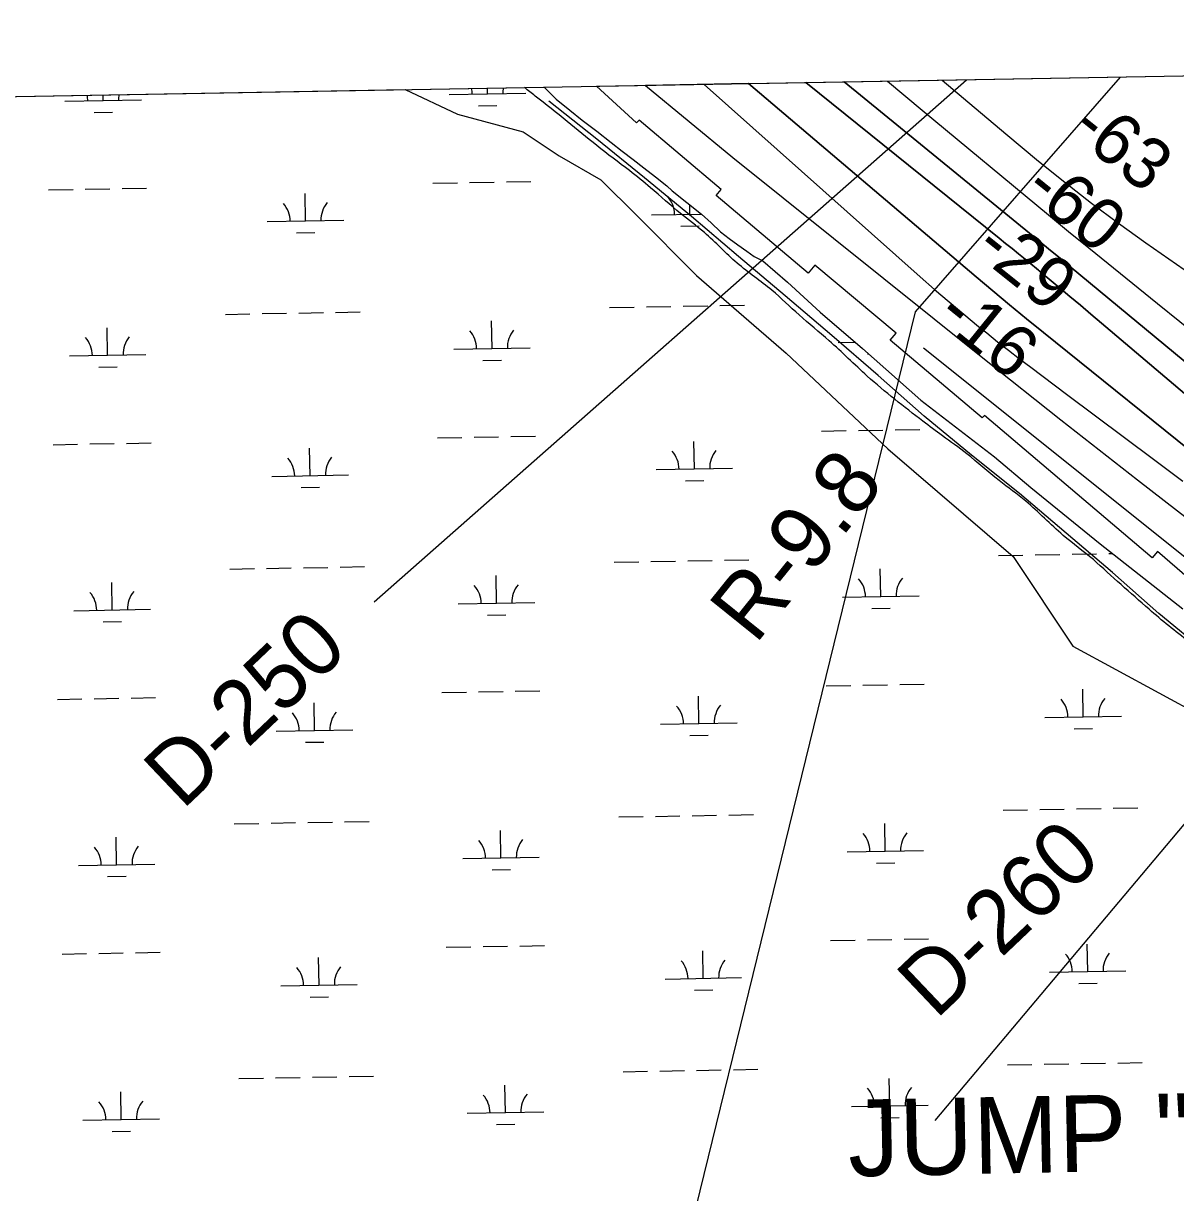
# Model space of a CAD drawing. Extents: x 3903937 to 3942190, y 260677 to 286651.
# Drawn here: x 3914342 to 3915846, y 282878 to 284405 of the extents above; entities that cross this region are included whole.
import ezdxf

# ---------------------------------------------------------------- set-up
doc = ezdxf.new("R2010")
doc.units = 0
for name, color, linetype in [('V-CHAN-NAID', 7, 'Continuous'), ('V-GRID-FRAM', 7, 'Continuous'), ('V-RIVR-EDGE', 7, 'Continuous'), ('V-RIVR-RANG', 7, 'Continuous'), ('V-RIVR-RANG-IDEN', 7, 'Continuous'), ('V-RRAP-FSHR', 7, 'Continuous'), ('V-RRAP-RVMT', 7, 'Continuous'), ('V-SITE-VEGE', 7, 'Continuous'), ('V-TOPO-DPTH', 7, 'Continuous'), ('V-TOPO-MAJR', 7, 'Continuous'), ('V-TOPO-MINR', 7, 'Continuous'), ('V-UTIL-LINE', 7, 'Continuous'), ('V-WETL-SWMP', 7, 'Continuous')]:
    doc.layers.add(name, color=color, linetype=linetype)

msp = doc.modelspace()

# ---------------------------------------------------------------- linework, layer by layer
at = {"layer": 'V-GRID-FRAM'}
msp.add_lwpolyline([(3907892.2, 284196.1), (3939773.2, 284757.2), (3940101.1, 266577.6), (3908204.3, 266016.2), (3907892.2, 284196.1)], dxfattribs=at)
at = {"layer": 'V-RIVR-EDGE'}
for points in [[(3915738.9, 283704.7), (3915699.6, 283736.4), (3915674.9, 283758.8), (3915650.7, 283781.1), (3915615.8, 283807.9), (3915573.6, 283843), (3915541.7, 283866.4), (3915516.4, 283885.4), (3915443.7, 283944.3), (3915393.8, 283990.6), (3915354.6, 284024.2), (3915319.2, 284056.4), (3915273.7, 284091.9), (3915231, 284131.8), (3915200, 284156.7), (3915160.7, 284190.3), (3915133.1, 284212.7), (3915090.5, 284245.3), (3915051.7, 284277), (3915010, 284310.1), (3914995.9, 284321.1)], [(3917425.1, 282263.8), (3917389, 282294.2), (3917376.9, 282301.5), (3917364.7, 282305.9), (3917358.9, 282312.7), (3917351.7, 282313.2), (3917339.5, 282313.8), (3917337.6, 282316.7), (3917335.7, 282327.9), (3917333.2, 282330.8), (3917324.5, 282334.2), (3917318.2, 282334.7), (3917313.8, 282338.1), (3917308, 282350.3), (3917295.5, 282366.8), (3917283.8, 282379), (3917272.2, 282386.3), (3917256.7, 282392.6), (3917245, 282398), (3917231.4, 282406.8), (3917219.3, 282412.6), (3917183.4, 282425.8), (3917138.3, 282440), (3917074.7, 282459.6), (3917032, 282479.1), (3916988.4, 282500.1), (3916967.5, 282515.7), (3916953.5, 282531.3), (3916939.4, 282546.9), (3916923.4, 282556.6), (3916909.4, 282558.6), (3916896.3, 282564), (3916886.6, 282574.7), (3916876.4, 282580.1), (3916858.4, 282585), (3916838.5, 282588.4), (3916812.3, 282597.2), (3916792, 282609.9), (3916782.3, 282615.7), (3916776, 282619.6), (3916763.8, 282627.4), (3916749.3, 282634.3), (3916741, 282637.7), (3916730.4, 282642.1), (3916723.6, 282648.4), (3916721.7, 282654.3), (3916721.7, 282661.1), (3916724.1, 282668.3), (3916732.9, 282687.7), (3916733.4, 282696), (3916730.5, 282710.6), (3916725.2, 282723.7), (3916724.8, 282730.5), (3916727.2, 282735.3), (3916735.5, 282744.1), (3916736.9, 282748.4), (3916736.5, 282752.3), (3916730.2, 282755.7), (3916729.2, 282758.2), (3916731.6, 282760.1), (3916731.6, 282763.5), (3916727.8, 282770.8), (3916727.3, 282772.7), (3916727.8, 282778.1), (3916727.8, 282783.9), (3916726.9, 282799), (3916725.5, 282818.4), (3916729.9, 282838.8), (3916731.4, 282846.1), (3916733.8, 282854.8), (3916737.7, 282862.1), (3916742.1, 282864.5), (3916751.8, 282863.5), (3916755.7, 282865.4), (3916757.2, 282868.8), (3916756.2, 282873.2), (3916756.2, 282883.9), (3916757.7, 282894.1), (3916764, 282902.3), (3916767, 282910.1), (3916770.4, 282913), (3916781, 282908.1), (3916789.3, 282907.6), (3916789.3, 282910), (3916782, 282918.8), (3916778.7, 282923.6), (3916763.6, 282935.3), (3916726.8, 282963.6), (3916714.2, 282972.9), (3916689, 282991.4), (3916632.3, 283034.2), (3916610, 283048.9), (3916578, 283066.9), (3916543, 283088.9), (3916510.1, 283112.7), (3916469.8, 283140.5), (3916444.2, 283160.5), (3916369, 283219), (3916281.3, 283284.2), (3916175.1, 283366.6), (3916089.8, 283429.9), (3915988, 283506.4), (3915917.7, 283560), (3915863.9, 283597.5), (3915811.6, 283639.9), (3915738.9, 283704.7)]]:
    msp.add_spline(points, degree=3, dxfattribs=at)
at = {"layer": 'V-RIVR-RANG'}
for p, q in [((3914800, 283649.7), (3915573.3, 284331.3)), ((3915532.3, 282972.2), (3916510.4, 284135.6))]:
    msp.add_line(p, q, dxfattribs=at)
at = {"layer": 'V-RRAP-FSHR'}
msp.add_lwpolyline([(3915885.9, 283583.8), (3915824.2, 283634.5), (3915763.8, 283687.8), (3915703.3, 283739.4), (3915642.5, 283790.9), (3915579.9, 283841.3), (3915518, 283891.9), (3915458.1, 283945), (3915397.5, 283997.2), (3915336.5, 284049), (3915275.4, 284100.6), (3915214.1, 284152.6), (3915152.6, 284203.2), (3915090.5, 284253.6), (3915027.9, 284303.4)], dxfattribs=at)
at = {"layer": 'V-RRAP-RVMT'}
for p, q in [((3915090, 284322.8), (3915958.5, 284338.1)), ((3915142.3, 284275.1), (3915090, 284322.8)), ((3915145.7, 284278.7), (3915142.3, 284275.1)), ((3915253.1, 284188), (3915145.7, 284278.7)), ((3915246.3, 284180.1), (3915253.1, 284188)), ((3915366.5, 284078.7), (3915246.3, 284180.1)), ((3915375.4, 284089.4), (3915366.5, 284078.7)), ((3915481.3, 284000.2), (3915375.4, 284089.4)), ((3915473.6, 283991.2), (3915481.3, 284000.2)), ((3915593.8, 283889.8), (3915473.6, 283991.2)), ((3915596.6, 283893.1), (3915593.8, 283889.8)), ((3915815.8, 283707), (3915596.6, 283893.1)), ((3915822.8, 283715.3), (3915815.8, 283707)), ((3915926.5, 283624.8), (3915822.8, 283715.3))]:
    msp.add_line(p, q, dxfattribs=at)
at = {"layer": 'V-SITE-VEGE'}
for p, q in [((3913226.6, 284290), (3914840.4, 284318.4)), ((3914840.4, 284318.4), (3914908.5, 284286.6)), ((3914908.5, 284286.6), (3914994.4, 284263.2)), ((3914994.4, 284263.2), (3915041.2, 284231.9)), ((3915041.2, 284231.9), (3915095.8, 284200.7)), ((3915095.8, 284200.7), (3915142.6, 284153.9)), ((3915142.6, 284153.9), (3915220.7, 284075.8)), ((3915220.7, 284075.8), (3915337.7, 283974.3)), ((3915337.7, 283974.3), (3915470.4, 283849.4)), ((3915470.4, 283849.4), (3915634.2, 283708.9)), ((3915634.2, 283708.9), (3915712.2, 283591.8)), ((3915712.2, 283591.8), (3915883.9, 283498.1))]:
    msp.add_line(p, q, dxfattribs=at)
at = {"layer": 'V-TOPO-DPTH'}
msp.add_line((3915288.4, 284326.3), (3915154, 284323.9), dxfattribs=at)
for points in [[(3915154, 284323.9), (3915210.9, 284276.7), (3915268.2, 284230), (3915596.7, 283966.6), (3915696.3, 283887.4), (3915796.4, 283808.7), (3915897.2, 283731)], [(3915895.2, 283822.9), (3915673.8, 284001.2), (3915651.6, 284019.2), (3915629.5, 284037.4), (3915607.5, 284055.7), (3915585.7, 284074.1), (3915288.4, 284326.3)], [(3915288.4, 284326.3), (3915585.7, 284074.1), (3915607.5, 284055.7), (3915629.5, 284037.4), (3915651.6, 284019.2), (3915673.8, 284001.2), (3915895.2, 283822.9)], [(3916245.8, 283593.1), (3915749.5, 284013.5), (3915735.7, 284025.2), (3915721.9, 284036.9), (3915708, 284048.5), (3915694.2, 284060.2), (3915668.2, 284082), (3915667.4, 284082.7), (3915664.8, 284084.8), (3915649.7, 284097.1), (3915641.2, 284104), (3915632.8, 284110.8), (3915624.3, 284117.7), (3915615.9, 284124.5), (3915363.6, 284327.6)], [(3916245.8, 283593.1), (3915749.5, 284013.5), (3915735.7, 284025.2), (3915721.9, 284036.9), (3915708, 284048.5), (3915694.2, 284060.2), (3915668.2, 284082), (3915667.4, 284082.7), (3915664.8, 284084.8), (3915649.7, 284097.1), (3915641.2, 284104), (3915632.8, 284110.8), (3915624.3, 284117.7), (3915615.9, 284124.5), (3915363.6, 284327.6)], [(3915413.4, 284328.5), (3915660.4, 284127), (3915672.8, 284116.8), (3915685.2, 284106.6), (3915697.6, 284096.4), (3915710, 284086.2), (3916138.8, 283731.5)], [(3916138.8, 283731.5), (3915710, 284086.2), (3915697.6, 284096.4), (3915685.2, 284106.6), (3915672.8, 284116.8), (3915660.4, 284127), (3915413.4, 284328.5)]]:
    msp.add_lwpolyline(points, dxfattribs=at)
at = {"layer": 'V-TOPO-MAJR'}
msp.add_lwpolyline([(3915469.9, 284329.5), (3915515.3, 284291.7), (3915680.3, 284154.8), (3915693.4, 284144), (3915706.6, 284133.2), (3915719.7, 284122.4), (3915732.9, 284111.7), (3915822.6, 284039), (3915880.8, 283992)], dxfattribs=at)
at = {"layer": 'V-TOPO-MINR'}
for points in [[(3915154, 284323.9), (3915210.9, 284276.7), (3915268.2, 284230), (3915596.7, 283966.6), (3915696.3, 283887.4), (3915796.4, 283808.7), (3915897.2, 283731), (3915998.4, 283653.8), (3916141.4, 283545.9), (3916171.5, 283523.1), (3916201.5, 283500.4), (3916231.6, 283477.6), (3916261.6, 283454.7), (3916269, 283449.1), (3916302.5, 283423.3), (3916335.9, 283397.3), (3916369, 283370.9), (3916401.9, 283344.3), (3916773.8, 283040.4), (3916800.9, 283018), (3916827.8, 282995.5), (3916854.4, 282972.6), (3916880.9, 282949.6), (3916960.8, 282879.2)], [(3915230.6, 284325.3), (3915512.8, 284074.1), (3915531.6, 284057.6), (3915550.6, 284041.2), (3915569.7, 284025.1), (3915589.1, 284009.3), (3915599.6, 284000.7), (3915613.9, 283989.3), (3915628.2, 283978), (3915642.6, 283966.9), (3915657.2, 283955.9), (3915703.8, 283920.9), (3915741.7, 283892.5), (3915779.6, 283864.1), (3915817.6, 283835.7), (3915855.5, 283807.3)], [(3915288.4, 284326.3), (3915585.7, 284074.1), (3915607.5, 284055.7), (3915629.5, 284037.4), (3915651.6, 284019.2), (3915673.8, 284001.2), (3915895.2, 283822.9)], [(3915363.6, 284327.6), (3915615.9, 284124.5), (3915624.3, 284117.7), (3915632.8, 284110.8), (3915641.2, 284104), (3915649.7, 284097.1), (3915664.8, 284084.8), (3915667.4, 284082.7), (3915668.2, 284082), (3915694.2, 284060.2), (3915708, 284048.5), (3915721.9, 284036.9), (3915735.7, 284025.2), (3915749.5, 284013.5), (3916245.8, 283593.1)], [(3915413.4, 284328.5), (3915660.4, 284127), (3915672.8, 284116.8), (3915685.2, 284106.6), (3915697.6, 284096.4), (3915710, 284086.2), (3916138.8, 283731.5)], [(3915541.5, 284330.7), (3915569.3, 284307.1), (3915624.5, 284260.8), (3915667.3, 284225.2), (3915701.6, 284197.4), (3915736.3, 284170.2), (3915771.7, 284143.9), (3915807.6, 284118.3), (3915997.5, 283985.9)], [(3915517.1, 283981.1), (3915943, 283640.3), (3915980.6, 283610.4), (3916018.4, 283580.7), (3916056.4, 283551.3), (3916094.6, 283522.1), (3916113.7, 283507.5), (3916142.5, 283485.8), (3916171.3, 283464.1), (3916200.1, 283442.5), (3916229.1, 283421), (3916398.9, 283295.1), (3916468.5, 283242.9), (3916537.7, 283190.1), (3916606.2, 283136.5), (3916674.4, 283082.3), (3916778, 282998.8), (3916793.9, 282985.9), (3916809.7, 282972.8), (3916825.3, 282959.5), (3916840.7, 282946), (3916896.5, 282897)]]:
    msp.add_lwpolyline(points, dxfattribs=at)
at = {"layer": 'V-UTIL-LINE'}
msp.add_lwpolyline([(3915773.8, 284334.8), (3915506, 284028.1), (3914530.5, 280044.6)], dxfattribs=at)
at = {"layer": 'V-WETL-SWMP'}
for p, q in [((3913193.2, 284289.4), (3915021.6, 284321.6)), ((3914446, 284304.2), (3914445.9, 284311.4)), ((3914897.8, 284312.1), (3914997.8, 284313.9)), ((3914947.8, 284313), (3914947.7, 284320.3)), ((3915021.6, 284321.6), (3915037.6, 284305.8)), ((3914396, 284303.3), (3914496, 284305.1)), ((3914936.1, 284297.4), (3914960.1, 284297.8)), ((3915037.6, 284305.8), (3915055.2, 284291.6)), ((3914434.3, 284288.5), (3914458.3, 284289)), ((3915055.2, 284291.6), (3915071.4, 284278.6)), ((3915071.4, 284278.6), (3915090.4, 284264.2)), ((3915090.4, 284264.2), (3915109.4, 284249.4)), ((3915109.4, 284249.4), (3915123.8, 284238.2)), ((3915123.8, 284238.2), (3915138, 284227.2)), ((3915138, 284227.2), (3915151.8, 284216.2)), ((3915151.8, 284216.2), (3915167, 284204.6)), ((3915167, 284204.6), (3915181.8, 284193)), ((3914374.6, 284187.5), (3914406.6, 284188)), ((3914422.6, 284188.3), (3914454.6, 284188.9)), ((3914470.6, 284189.2), (3914502.6, 284189.7)), ((3914876.4, 284196.3), (3914908.4, 284196.9)), ((3914924.4, 284197.1), (3914956.4, 284197.7)), ((3914972.4, 284198), (3915004.4, 284198.6)), ((3915181.8, 284193), (3915189, 284186.4)), ((3915189, 284186.4), (3915227, 284155.8)), ((3914710.2, 284146.9), (3914709.6, 284182.9)), ((3915162.1, 284154.9), (3915226.8, 284156)), ((3915212.1, 284155.8), (3915211.8, 284168.1)), ((3915227, 284155.8), (3915239.8, 284144.7)), ((3914660.2, 284146.1), (3914760.2, 284147.8)), ((3915200.3, 284140.1), (3915224.3, 284140.6)), ((3915239.8, 284144.7), (3915252.2, 284132.9)), ((3914698.5, 284131.3), (3914722.5, 284131.7)), ((3915252.2, 284132.9), (3915263.4, 284124.1)), ((3915263.4, 284124.1), (3915274.6, 284115.9)), ((3915274.6, 284115.9), (3915286.2, 284107.3)), ((3915286.2, 284107.3), (3915295.8, 284100.5)), ((3915295.8, 284100.5), (3915307.2, 284094.8)), ((3915307.2, 284094.8), (3915339.6, 284067.2)), ((3915339.6, 284067.2), (3915382.3, 284028)), ((3915107.3, 284033.8), (3915139.3, 284034.4)), ((3915155.3, 284034.7), (3915187.3, 284035.2)), ((3915203.3, 284035.5), (3915235.3, 284036.1)), ((3915251.3, 284036.4), (3915283.3, 284036.9)), ((3914605.5, 284025), (3914637.5, 284025.6)), ((3914653.5, 284025.9), (3914685.5, 284026.4)), ((3914701.5, 284026.7), (3914733.5, 284027.3)), ((3914749.5, 284027.5), (3914781.5, 284028.1)), ((3915382.3, 284028), (3915437.4, 283980.3)), ((3914451.8, 283971.6), (3914451.2, 284007.5)), ((3914953.7, 283980.4), (3914953, 284016.4)), ((3915405.5, 283988.3), (3915427.7, 283988.7)), ((3914401.8, 283970.7), (3914501.8, 283972.4)), ((3914903.7, 283979.5), (3915003.7, 283981.3)), ((3915437.4, 283980.3), (3915513.4, 283913.1)), ((3915443.8, 283973.6), (3915445, 283973.6)), ((3914440.1, 283955.9), (3914464.1, 283956.3)), ((3914941.9, 283964.7), (3914965.9, 283965.2)), ((3915513.4, 283913.1), (3915609.6, 283838.9)), ((3914882.3, 283863.7), (3914914.3, 283864.2)), ((3914930.3, 283864.5), (3914962.3, 283865.1)), ((3914978.3, 283865.4), (3915010.3, 283865.9)), ((3915384.1, 283872.5), (3915416.1, 283873.1)), ((3915432.1, 283873.4), (3915464.1, 283873.9)), ((3915480.1, 283874.2), (3915512.1, 283874.8)), ((3914380.5, 283854.8), (3914412.5, 283855.4)), ((3914428.5, 283855.7), (3914460.5, 283856.3)), ((3914476.5, 283856.5), (3914508.5, 283857.1)), ((3914716.1, 283814.3), (3914715.4, 283850.3)), ((3915217.9, 283823.1), (3915217.3, 283859.1)), ((3915609.6, 283838.9), (3915657.2, 283798.9)), ((3915167.9, 283822.3), (3915267.9, 283824)), ((3914666.1, 283813.4), (3914766.1, 283815.2)), ((3915206.2, 283807.5), (3915230.2, 283807.9)), ((3914704.4, 283798.7), (3914728.4, 283799.1)), ((3915657.2, 283798.9), (3915747.6, 283725.1)), ((3915711, 283711.7), (3915743, 283712.3)), ((3915747.6, 283725.1), (3915855.9, 283640.6)), ((3915759, 283712.6), (3915763.6, 283712.7)), ((3915113.2, 283701.2), (3915145.2, 283701.8)), ((3915161.2, 283702.1), (3915193.2, 283702.6)), ((3915209.2, 283702.9), (3915241.2, 283703.5)), ((3915257.2, 283703.8), (3915289.2, 283704.3)), ((3915615, 283710), (3915647, 283710.6)), ((3915663, 283710.9), (3915695, 283711.5)), ((3914611.4, 283692.4), (3914643.4, 283692.9)), ((3914659.4, 283693.2), (3914691.4, 283693.8)), ((3914707.4, 283694.1), (3914739.3, 283694.6)), ((3914755.3, 283694.9), (3914787.3, 283695.5)), ((3914959.5, 283647.8), (3914958.9, 283683.8)), ((3915461.4, 283656.6), (3915460.7, 283692.6)), ((3914457.7, 283638.9), (3914457.1, 283674.9)), ((3915411.4, 283655.7), (3915511.3, 283657.5)), ((3914407.7, 283638), (3914507.7, 283639.8)), ((3914909.5, 283646.9), (3915009.5, 283648.6)), ((3915449.6, 283641), (3915473.6, 283641.4)), ((3914446, 283623.3), (3914470, 283623.7)), ((3914947.8, 283632.1), (3914971.8, 283632.5)), ((3914888.2, 283531.1), (3914920.2, 283531.6)), ((3914936.1, 283531.9), (3914968.1, 283532.5)), ((3914984.1, 283532.7), (3915016.1, 283533.3)), ((3915390, 283539.9), (3915422, 283540.5)), ((3915438, 283540.7), (3915470, 283541.3)), ((3915486, 283541.6), (3915518, 283542.1)), ((3915725.6, 283499.4), (3915725, 283535.4)), ((3914386.3, 283522.2), (3914418.3, 283522.8)), ((3914434.3, 283523.1), (3914466.3, 283523.6)), ((3914482.3, 283523.9), (3914514.3, 283524.5)), ((3914721.9, 283481.7), (3914721.3, 283517.7)), ((3915223.8, 283490.5), (3915223.1, 283526.5)), ((3915675.6, 283498.5), (3915775.6, 283500.2)), ((3914671.9, 283480.8), (3914771.9, 283482.6)), ((3915173.8, 283489.6), (3915273.8, 283491.4)), ((3915713.9, 283483.7), (3915737.9, 283484.1)), ((3915212, 283474.9), (3915236, 283475.3)), ((3914710.2, 283466.1), (3914734.2, 283466.5)), ((3915620.9, 283377.4), (3915652.9, 283378)), ((3915668.9, 283378.3), (3915700.9, 283378.8)), ((3915716.9, 283379.1), (3915748.9, 283379.7)), ((3915764.9, 283380), (3915796.9, 283380.5)), ((3914665.2, 283360.6), (3914697.2, 283361.2)), ((3914713.2, 283361.4), (3914745.2, 283362)), ((3914761.2, 283362.3), (3914793.2, 283362.9)), ((3915119.1, 283368.6), (3915151, 283369.2)), ((3915167, 283369.4), (3915199, 283370)), ((3915215, 283370.3), (3915247, 283370.8)), ((3915263, 283371.1), (3915295, 283371.7)), ((3914617.2, 283359.8), (3914649.2, 283360.3)), ((3914965.4, 283315.1), (3914964.7, 283351.1)), ((3915467.2, 283324), (3915466.6, 283360)), ((3914463.5, 283306.3), (3914462.9, 283342.3)), ((3914915.4, 283314.3), (3915015.4, 283316)), ((3915417.2, 283323.1), (3915517.2, 283324.9)), ((3914413.6, 283305.4), (3914513.5, 283307.2)), ((3914953.7, 283299.5), (3914977.6, 283299.9)), ((3915455.5, 283308.3), (3915479.5, 283308.8)), ((3914451.8, 283290.7), (3914475.8, 283291.1)), ((3915395.8, 283207.3), (3915427.8, 283207.8)), ((3915443.8, 283208.1), (3915475.8, 283208.7)), ((3915491.8, 283209), (3915523.8, 283209.5)), ((3914894, 283198.4), (3914926, 283199)), ((3914942, 283199.3), (3914974, 283199.8)), ((3914990, 283200.1), (3915022, 283200.7)), ((3915229.6, 283157.9), (3915229, 283193.9)), ((3915731.5, 283166.7), (3915730.8, 283202.7)), ((3914392.2, 283189.6), (3914424.2, 283190.2)), ((3914440.2, 283190.4), (3914472.2, 283191)), ((3914488.2, 283191.3), (3914520.2, 283191.9)), ((3914727.8, 283149.1), (3914727.2, 283185.1)), ((3915681.5, 283165.9), (3915781.4, 283167.6)), ((3914677.8, 283148.2), (3914777.8, 283149.9)), ((3915179.6, 283157), (3915279.6, 283158.8)), ((3915719.7, 283151.1), (3915743.7, 283151.5)), ((3914716.1, 283133.4), (3914740.1, 283133.9)), ((3915217.9, 283142.3), (3915241.9, 283142.7)), ((3915626.7, 283044.8), (3915658.7, 283045.4)), ((3915674.7, 283045.6), (3915706.7, 283046.2)), ((3915722.7, 283046.5), (3915754.7, 283047.1)), ((3915770.7, 283047.3), (3915802.7, 283047.9)), ((3914623.1, 283027.1), (3914655.1, 283027.7)), ((3914671.1, 283028), (3914703.1, 283028.5)), ((3914719.1, 283028.8), (3914751.1, 283029.4)), ((3914767.1, 283029.7), (3914799, 283030.2)), ((3915124.9, 283036), (3915156.9, 283036.5)), ((3915172.9, 283036.8), (3915204.9, 283037.4)), ((3915220.9, 283037.7), (3915252.9, 283038.2)), ((3915268.9, 283038.5), (3915300.9, 283039.1)), ((3915473.1, 282991.3), (3915472.4, 283027.3)), ((3914469.4, 282973.7), (3914468.8, 283009.7)), ((3914971.2, 282982.5), (3914970.6, 283018.5)), ((3914921.2, 282981.6), (3915021.2, 282983.4)), ((3915423.1, 282990.5), (3915523.1, 282992.2)), ((3914419.4, 282972.8), (3914519.4, 282974.6)), ((3914959.5, 282966.9), (3914983.5, 282967.3)), ((3915461.3, 282975.7), (3915485.3, 282976.1)), ((3914457.7, 282958), (3914481.7, 282958.5))]:
    msp.add_line(p, q, dxfattribs=at)
for centre, start, end in [((3914390.7, 284303.7), 0.2366, 12.1323), ((3914501.2, 284305.6), 169.8845, 181.7802), ((3914892.6, 284312.5), 0.2366, 12.1317), ((3915003, 284314.5), 169.8851, 181.7802), ((3914655, 284146.4), 0.2366, 41.7802), ((3914765.5, 284148.4), 140.2366, 181.7802), ((3915156.8, 284155.3), 0.2366, 41.7802), ((3914898.4, 283979.9), 0.2366, 41.7802), ((3915008.9, 283981.8), 140.2366, 181.7802), ((3914396.6, 283971.1), 0.2366, 41.7802), ((3914507.1, 283973), 140.2366, 181.7802), ((3914660.8, 283813.8), 0.2366, 41.7802), ((3914771.3, 283815.8), 140.2366, 181.7802), ((3915162.7, 283822.7), 0.2366, 41.7802), ((3915273.1, 283824.6), 140.2366, 181.7802), ((3914904.3, 283647.3), 0.2366, 41.7802), ((3915014.7, 283649.2), 140.2366, 181.7802), ((3915406.1, 283656.1), 0.2366, 41.7802), ((3915516.6, 283658), 140.2366, 181.7802), ((3914402.4, 283638.4), 0.2366, 41.7802), ((3914512.9, 283640.4), 140.2366, 181.7802), ((3915168.5, 283490), 0.2366, 41.7802), ((3915279, 283492), 140.2366, 181.7802), ((3915670.4, 283498.9), 0.2366, 41.7802), ((3915780.8, 283500.8), 140.2366, 181.7802), ((3914666.7, 283481.2), 0.2366, 41.7802), ((3914777.2, 283483.1), 140.2366, 181.7802), ((3915412, 283323.5), 0.2366, 41.7802), ((3915522.4, 283325.4), 140.2366, 181.7802), ((3914518.8, 283307.8), 140.2366, 181.7802), ((3914910.1, 283314.6), 0.2366, 41.7802), ((3915020.6, 283316.6), 140.2366, 181.7802), ((3914408.3, 283305.8), 0.2366, 41.7802), ((3915174.4, 283157.4), 0.2366, 41.7802), ((3915284.8, 283159.3), 140.2366, 181.7802), ((3915676.2, 283166.2), 0.2366, 41.7802), ((3915786.7, 283168.2), 140.2366, 181.7802), ((3914672.5, 283148.6), 0.2366, 41.7802), ((3914783, 283150.5), 140.2366, 181.7802), ((3915417.8, 282990.9), 0.2366, 41.7802), ((3915528.3, 282992.8), 140.2366, 181.7802), ((3914414.2, 282973.2), 0.2366, 41.7802), ((3914524.6, 282975.1), 140.2366, 181.7802), ((3914916, 282982), 0.2366, 41.7802), ((3915026.5, 282984), 140.2366, 181.7802)]:
    msp.add_arc(centre, 35.2, start, end, dxfattribs=at)

# ---------------------------------------------------------------- texts
at = {"layer": 'V-CHAN-NAID'}
msp.add_text('JUMP "9" (9.8)', height=100, rotation=1.1211, dxfattribs=at).set_placement((3915419.3, 282899.2))
at = {"layer": 'V-RIVR-RANG'}
for s, rotation, p in [('-63', 321.3196, (3915705.9, 284262.3)), ('-60', 321.3196, (3915645.1, 284182.9)), ('-29', 321.3196, (3915580.8, 284106.3)), ('-16', 321.0383, (3915531.1, 284018.3))]:
    msp.add_text(s, height=67, rotation=rotation, dxfattribs=at).set_placement(p)
at = {"layer": 'V-RIVR-RANG-IDEN'}
for s, rotation, p in [('R-9.8', 51.178, (3915297.6, 283592.7)), ('D-250', 43.5009, (3914549.3, 283376.9)), ('D-260', 43.5009, (3915533.2, 283103.1))]:
    msp.add_text(s, height=83, rotation=rotation, dxfattribs=at).set_placement(p)

doc.saveas('drawing.dxf')
